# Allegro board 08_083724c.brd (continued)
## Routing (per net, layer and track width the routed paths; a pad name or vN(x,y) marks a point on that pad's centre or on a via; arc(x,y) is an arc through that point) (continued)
DAI1_PIN17: length 16.3
  TOP w0.14: P8.64 26.75,66.79 26.85,66.69 26.85,65.93 v1(26.5,65.58) ; U1.AB19 35.35,59.84 v1(35.13,60.06)
  L3_SIG1 w0.114: v1(26.5,65.58) 26.11,65.2 26.11,64.9 29.52,61.49 33.7,61.49 v1(35.13,60.06)
DAI1_PIN18: length 16.5
  TOP w0.14: v1(26.5,65.07) 27.13,65.71 27.13,66.73 27.25,66.84 P8.66 ; U1.AB18 v1(35.75,59.02)
  L3_SIG1 w0.114: v1(35.75,59.02) 35.75,59.97 33.92,61.8 29.77,61.8 v1(26.5,65.07)
DAI1_PIN19: length 15.1
  TOP w0.14: v1(27.5,65.58) 27.85,65.93 27.85,66.69 27.75,66.79 P8.68 ; U1.AA19 v1(34.95,58.22)
  L5_SIG2 w0.114: v1(34.95,58.22) 33.88,59.28 33.88,60.45 32.64,61.7 31.04,61.7 27.97,64.77 27.97,65.47 27.85,65.58 v1(27.5,65.58)
DAI1_PIN20: length 17.1
  TOP w0.14: v1(27.5,65.07) 28.13,65.71 28.13,66.73 28.25,66.84 P8.70 ; U1.AA18 v1(35.75,58.22)
  L3_SIG1 w0.114: v1(27.5,65.07) 27.5,64.65 30.03,62.12 34.05,62.12 36.14,60.03 36.14,58.61 v1(35.75,58.22)
DMI0_A: length 26.4
  TOP w0.14: U1.A20 v1(34.15,41.42)
  L10_SIG4 w0.109: v1(34.15,41.42) 33.89,41.42 33.73,41.26 33.73,40.69 34.62,39.8 34.62,38.02 34.51,37.92 34.26,37.92 34.16,38.03 34.16,39.69 34.05,39.8 33.83,39.8 33.72,39.69 33.72,38.03 33.61,37.92 33.36,37.92 33.25,38.03 33.25,40.71 33.14,40.82 32.52,40.82 32.41,40.71 32.41,40.27 32.52,40.16 32.8,40.16 32.91,40.05 32.91,39.83 32.8,39.72 32.52,39.72 32.41,39.61 32.41,39.4 32.52,39.29 32.8,39.29 32.91,39.18 32.91,38.96 32.8,38.85 32.52,38.85 32.41,38.74 32.41,32.77 32.52,32.66 35.13,32.66 v1(35.5,32.3)
  BOTTOM w0.14: U3.C3 v1(35.5,32.3)
DMI0_B: length 28.8
  TOP w0.14: U1.B8 v1(44.55,42.22)
  L8_SIG3 w0.109: v1(47.2,32.3) 47.2,31.98 47.12,31.9 46.92,31.9 46.84,31.98 46.84,34.05 47.26,34.47 48.4,34.47 48.5,34.58 48.5,34.99 48.61,35.1 48.83,35.1 48.94,34.99 48.94,34.6 49.05,34.49 49.27,34.49 49.38,34.6 49.38,34.99 49.49,35.1 49.71,35.1 49.81,34.99 49.81,34.6 49.92,34.49 50.14,34.49 50.25,34.6 50.25,34.99 50.36,35.1 50.58,35.1 50.69,34.99 50.69,34.32 50.8,34.21 51.02,34.21 51.13,34.32 51.13,34.99 51.23,35.1 51.45,35.1 51.56,34.99 51.56,34.32 51.67,34.21 52.06,34.21 52.17,34.32 52.17,35.79 51.26,36.7 51.26,39.88 51,40.13 49.48,40.13 48.92,40.69 47.96,40.69 47.37,41.27 47.37,42.49 47.24,42.62 44.96,42.62 v1(44.55,42.22)
  BOTTOM w0.14: U3.Y3 v1(47.2,32.3)
DMI1_A: length 26.7
  TOP w0.14: U1.B15 v1(38.15,42.22)
  L8_SIG3 w0.109: v1(35.5,26.7) 36.27,26.7 36.4,26.82 36.4,26.98 36.29,27.09 35.63,27.09 35.52,27.2 35.52,27.41 35.63,27.52 36.29,27.52 36.4,27.63 36.4,28.5 36.2,28.7 34.62,28.7 34.47,28.85 34.47,30.96 34.34,31.09 33.76,31.09 33.66,31.2 33.66,31.8 33.76,31.9 35.82,31.9 35.92,32 35.92,33.35 35.81,33.46 35.31,33.46 35.2,33.57 35.2,33.8 35.3,33.89 35.71,33.89 35.84,34.02 35.84,34.2 35.71,34.33 35.27,34.33 35.1,34.5 35.1,34.9 35.28,35.08 35.79,35.08 35.94,35.23 35.94,39.42 37.73,41.21 37.73,41.54 38.05,41.86 v1(38.15,42.22)
  BOTTOM w0.14: U3.C10 v1(35.5,26.7)
DMI1_B: length 29
  TOP w0.14: U1.A2 v1(49.35,41.42)
  L10_SIG4 w0.109: v1(46.55,26.7) 46.74,26.88 46.74,27.89 47.04,28.19 49.66,28.19 50.52,29.06 50.52,30.63 50.63,30.74 51.53,30.74 51.64,30.85 51.64,31.07 51.53,31.17 50.6,31.17 50.5,31.28 50.5,31.5 50.6,31.61 51.53,31.61 51.64,31.72 51.64,31.94 51.53,32.05 50.58,32.05 50.47,32.16 50.47,32.38 50.58,32.49 51.53,32.49 51.64,32.59 51.64,32.81 51.53,32.92 50.76,32.92 50.65,33.03 50.65,33.25 50.76,33.36 51.53,33.36 51.64,33.47 51.64,33.69 51.53,33.8 51.26,33.8 51.16,33.9 51.16,34.12 51.64,34.61 51.64,37.89 51.53,38 51.29,38 51.18,38.11 51.18,38.33 51.29,38.44 51.53,38.44 51.64,38.55 51.64,38.77 51.53,38.87 51.29,38.87 51.18,38.98 51.18,39.2 51.29,39.31 51.53,39.31 51.64,39.42 51.64,39.8 50.57,40.87 49.89,40.87 v1(49.35,41.42)
  BOTTOM w0.14: U3.Y10 v1(46.55,26.7)
DQ0_A: length 27
  TOP w0.14: U1.C17 v1(36.55,43.02)
  L10_SIG4 w0.109: v1(36.55,43.02) 36.87,43.02 36.98,42.91 36.98,41.94 36.87,41.83 36.27,41.83 36.14,41.96 36.14,42.42 35.97,42.6 34.81,42.6 34.56,42.34 34.56,40.56 35.27,39.85 35.27,37.91 34.81,37.45 33.16,37.45 32.97,37.26 32.97,37.05 33.14,36.88 34.37,36.88 34.49,36.75 34.49,36.5 34.37,36.37 33.01,36.37 32.91,36.26 32.91,36.04 33.01,35.93 34.37,35.93 34.49,35.8 34.49,35.55 34.37,35.42 33.01,35.42 32.91,35.31 32.91,35.04 33.09,34.86 34.21,34.86 34.41,34.66 34.41,34.44 33.82,33.86 33.06,33.86 32.96,33.75 32.96,33.47 33.1,33.32 33.92,33.32 34.49,33.9 v1(34.85,33.9)
  BOTTOM w0.14: U3.B2 v1(34.85,33.9)
DQ0_B: length 29.5
  TOP w0.14: U1.D7 v1(45.35,43.82)
  L8_SIG3 w0.109: v1(47.85,33.1) 48.23,33.48 49.15,33.48 49.66,32.97 49.66,31.27 50.77,30.15 52.45,30.15 53.67,31.37 53.67,41.07 53.11,41.63 50.87,41.63 50.69,41.81 49.99,41.81 49.73,42.06 49.73,42.47 49.58,42.62 48.44,42.62 48.24,42.82 48.24,43.13 47.96,43.42 46.05,43.42 45.66,43.82 v1(45.35,43.82)
  BOTTOM w0.14: U3.AA2 v1(47.85,33.1)
DQ1_A: length 26.5
  TOP w0.14: U1.E19 v1(34.95,44.62)
  L10_SIG4 w0.109: v1(34.95,44.62) 34.88,44.28 34.56,43.95 34.56,43.54 34.43,43.41 32.9,43.41 32.79,43.3 32.79,42.73 32.9,42.62 33.65,42.62 33.78,42.49 33.78,41.92 33.67,41.81 32.06,41.81 31.95,41.7 31.95,32.34 32.08,32.21 32.36,32.21 32.47,32.1 32.47,31.28 32.58,31.17 32.8,31.17 32.9,31.28 32.9,32.1 33.01,32.21 33.23,32.21 33.34,32.1 33.34,31.28 33.45,31.17 33.67,31.17 33.78,31.28 33.78,31.79 33.89,31.9 35.93,31.9 36.04,32.01 36.04,32.28 35.5,32.83 v1(35.5,33.1)
  BOTTOM w0.14: U3.C2 v1(35.5,33.1)
DQ1_B: length 28.3
  TOP w0.14: U1.C4 v1(47.75,43.02)
  L8_SIG3 w0.109: v1(47.75,43.02) 47.83,42.65 48.13,42.35 48.13,41.22 48.31,41.05 49.17,41.05 49.71,40.51 51.44,40.51 51.69,40.26 51.69,36.91 52.6,35.99 52.6,31.7 52.37,31.47 51.85,31.47 51.56,31.75 51.56,33.72 51.46,33.83 51.24,33.83 51.13,33.72 51.13,31.58 51.02,31.47 50.73,31.47 50.62,31.58 50.62,33.81 50.29,34.14 47.44,34.14 v1(47.2,33.9)
  BOTTOM w0.14: U3.Y2 v1(47.2,33.9)
DQ2_A: length 27.4
  TOP w0.14: U1.D16 v1(37.35,43.82)
  L10_SIG4 w0.109: v1(37.35,43.82) 37.62,43.82 38.02,43.41 38.48,43.41 38.56,43.48 38.56,44.96 38.66,45.06 39.24,45.06 39.34,44.96 39.34,43.51 39.45,43.41 40.06,43.41 40.16,43.51 40.16,44.96 40.26,45.06 40.84,45.06 40.94,44.95 40.94,35.38 40.72,35.15 40.33,35.15 40.22,35.04 40.22,33.61 40.11,33.5 39.89,33.5 39.78,33.61 39.78,35.12 39.68,35.23 38.46,35.23 38.35,35.12 38.35,34.4 38.25,34.29 37.19,34.29 37.08,34.18 37.08,34.18 v1(36.8,33.9)
  BOTTOM w0.14: U3.E2 v1(36.8,33.9)
DQ2_B: length 30.8
  TOP w0.14: U1.C6 v1(46.15,43.02)
  L8_SIG3 w0.109: v1(46.15,43.02) 45.79,43.02 45.39,43.41 44.31,43.41 44.15,43.25 44.15,42.09 44.4,41.83 44.85,41.83 44.96,41.72 44.96,41.1 45.06,41 45.33,41 45.79,40.54 45.79,38.15 45.94,38 49.99,38 50.11,37.87 50.11,36.46 49.98,36.32 49.69,36.32 49.58,36.43 49.58,37.43 49.47,37.54 49.26,37.54 49.15,37.43 49.15,36.43 49.04,36.32 48.82,36.32 48.71,36.43 48.71,37.43 48.6,37.54 48.38,37.54 48.27,37.43 48.27,36.43 48.16,36.32 47.95,36.32 47.84,36.43 47.84,37.43 47.73,37.54 47.51,37.54 47.4,37.43 47.4,36.43 47.29,36.32 47.07,36.32 46.96,36.43 46.96,37.43 46.85,37.54 46.63,37.54 46.53,37.43 46.53,36.62 45.49,35.59 45.49,35.13 45.64,34.98 45.64,34.15 v1(45.9,33.9)
  BOTTOM w0.14: U3.V2 v1(45.9,33.9)
DQ3_A: length 27.2
  TOP w0.14: U1.D18 v1(35.75,43.82)
  L10_SIG4 w0.109: v1(35.75,43.82) 36.16,44.22 37.69,44.22 37.77,44.3 37.77,44.81 38.13,45.16 38.13,45.34 38.23,45.44 41.61,45.44 41.73,45.31 41.73,42.06 41.34,41.67 41.34,35.24 41.12,35.03 41.12,32.11 40.92,31.9 38.51,31.9 38.3,32.11 38.3,33.79 38.19,33.9 v1(37.45,33.9)
  BOTTOM w0.14: U3.F2 v1(37.45,33.9)
DQ3_B: length 28.2
  TOP w0.14: U1.C2 v1(49.35,43.02)
  L8_SIG3 w0.109: v1(45.25,33.9) 45.22,33.9 44.88,34.24 44.88,36.02 45.36,36.5 45.36,36.74 45.26,36.84 44.38,36.84 44.27,36.95 44.27,37.17 44.38,37.28 45.26,37.28 45.36,37.39 45.36,37.79 45.26,37.9 44.25,37.9 44.15,38.01 44.15,38.23 44.25,38.34 45.26,38.34 45.36,38.45 45.36,38.71 45.26,38.81 44.25,38.81 44.15,38.92 44.15,39.14 44.25,39.25 45.26,39.25 45.36,39.36 45.36,39.58 45.26,39.69 44.25,39.69 44.15,39.8 44.15,40.02 44.25,40.13 45.15,40.13 45.26,40.23 45.26,40.45 45.15,40.56 44.4,40.56 44.15,40.82 44.15,41.63 43.94,41.83 43.56,41.83 43.32,42.08 43.32,43.98 43.59,44.25 47.89,44.25 48.16,43.98 48.16,43.66 48.4,43.42 48.95,43.42 v1(49.35,43.02)
  BOTTOM w0.14: U3.U2 v1(45.25,33.9)
DQ4_A: length 26.7
  TOP w0.14: U1.E17 v1(36.55,44.62)
  L10_SIG4 w0.109: v1(36.55,44.62) 36.94,45.01 37.49,45.01 37.74,45.26 37.74,45.67 37.92,45.85 42.44,45.85 42.55,45.74 42.55,42.34 41.76,41.55 41.76,35.07 41.48,34.79 41.48,31.83 40.74,31.09 37.86,31.09 v1(37.45,31.5)
  BOTTOM w0.14: U3.F4 v1(37.45,31.5)
DQ4_B: length 28.2
  TOP w0.14: U1.B1 v1(50.15,42.22)
  L8_SIG3 w0.109: v1(50.15,42.22) 50.87,42.22 51.13,41.96 53.57,41.96 54.18,41.35 54.18,30.28 53.72,29.82 44.55,29.82 44.35,30.02 44.35,31.24 v1(44.6,31.5)
  BOTTOM w0.14: U3.U4 v1(44.6,31.5)
DQ5_A: length 26.6
  TOP w0.14: U1.F18 v1(35.75,45.42)
  L10_SIG4 w0.109: v1(37.45,32.3) 37.79,32.3 37.9,32.41 37.9,33.32 37.71,33.5 36.64,33.5 36.25,33.89 36.25,34.14 37.69,35.59 40.39,35.59 40.54,35.74 40.54,37.77 40.26,38.05 39.81,38.05 39.67,38.18 39.67,39.45 40.06,39.83 40.45,39.83 40.56,39.94 40.56,40.84 40.45,40.94 40.28,40.94 40.16,41.07 40.16,41.72 40.05,41.83 39.43,41.83 39.32,41.94 39.32,42.51 39.21,42.62 38.67,42.62 38.56,42.51 38.56,41.96 38.43,41.83 37.95,41.83 37.74,42.04 37.74,43.18 37.52,43.41 35.5,43.41 35.32,43.59 35.32,44.74 35.66,45.09 v1(35.75,45.42)
  BOTTOM w0.14: U3.E4 v1(37.45,32.3)
DQ5_B: length 28.2
  TOP w0.14: U1.B5 v1(46.95,42.22)
  L8_SIG3 w0.109: v1(45.9,31.5) 46.22,31.69 46.56,32.03 46.56,34.19 47.22,34.85 47.88,34.85 47.96,34.92 47.96,35.36 48.08,35.48 51.4,35.48 51.51,35.59 51.51,35.87 50.88,36.5 50.88,39.55 50.7,39.73 49.33,39.73 49.09,39.97 48.89,39.97 48.78,39.86 48.78,39.1 48.67,38.99 48.46,38.99 48.35,39.1 48.35,40.18 48.24,40.28 48.02,40.28 47.91,40.18 47.91,39.1 47.8,38.99 47.58,38.99 47.47,39.1 47.47,40.58 47.36,40.69 47.15,40.69 47.04,40.58 47.04,39.1 46.93,38.99 46.71,38.99 46.56,39.14 46.56,41.82 v1(46.95,42.22)
  BOTTOM w0.14: U3.V4 v1(45.9,31.5)
DQ6_A: length 28.1
  TOP w0.14: U1.F16 v1(37.35,45.42)
  L10_SIG4 w0.109: v1(37.35,45.42) 36.96,45.81 36.96,46.42 36.75,46.63 35.6,46.63 35.36,46.38 35.36,46.08 35.12,45.83 34.75,45.83 34.54,45.63 34.54,45.26 34.3,45.02 31.88,45.02 31.09,44.22 31.09,31.47 32.26,30.3 35,30.3 35.23,30.53 35.23,31.22 v1(35.5,31.5)
  BOTTOM w0.14: U3.C4 v1(35.5,31.5)
DQ6_B: length 28.3
  TOP w0.14: U1.B7 v1(45.35,42.22)
  L8_SIG3 w0.109: v1(47.2,31.5) 47.58,31.11 48.18,31.11 48.29,31.01 48.29,30.36 48.18,30.25 45.09,30.25 44.86,30.48 44.86,31.22 45.54,31.9 46.02,31.9 46.28,32.16 46.28,34.3 46.18,34.4 46.18,34.9 47.17,35.89 50.41,35.89 50.56,36.04 50.56,38.87 50.29,39.14 49.5,39.14 48.89,38.52 46.41,38.52 46.19,38.74 46.19,40.75 45.75,41.2 45.75,41.82 v1(45.35,42.22)
  BOTTOM w0.14: U3.Y4 v1(47.2,31.5)
DQ7_A: length 26.5
  TOP w0.14: U1.G17 v1(36.55,46.22)
  L10_SIG4 w0.109: v1(36.55,46.22) 36.16,45.82 35.59,45.82 35.33,45.57 35.33,45.24 35.1,45.01 34.76,45.01 34.54,44.79 34.54,44.48 34.29,44.22 31.67,44.22 31.48,44.03 31.48,43.8 31.59,43.69 32.15,43.69 32.26,43.58 32.26,43.36 32.15,43.25 31.59,43.25 31.48,43.15 31.48,42.93 31.59,42.82 32.2,42.82 32.31,42.71 32.31,42.49 32.2,42.38 31.63,42.38 31.52,42.27 31.52,31.7 32.48,30.73 34.09,30.73 v1(34.85,31.5)
  BOTTOM w0.14: U3.B4 v1(34.85,31.5)
DQ7_B: length 28.2
  TOP w0.14: U1.B3 v1(48.55,42.22)
  L8_SIG3 w0.109: v1(47.85,31.5) 48.26,31.9 48.67,31.9 48.87,32.11 48.87,32.49 48.67,32.69 47.68,32.69 47.42,32.94 47.42,33.4 47.83,33.81 49.56,33.81 50.11,33.25 50.11,31.5 50.47,31.14 52.63,31.14 53.11,31.62 53.11,36.42 52.65,36.88 52.65,38.55 52.54,38.66 52.23,38.66 52.12,38.77 52.12,38.98 52.23,39.09 52.54,39.09 52.65,39.2 52.65,39.42 52.54,39.53 52.23,39.53 52.12,39.64 52.12,39.86 52.37,40.11 52.37,40.46 51.89,40.94 49.86,40.94 49.73,41.07 49.73,41.58 49.5,41.81 48.96,41.81 v1(48.55,42.22)
  BOTTOM w0.14: U3.AA4 v1(47.85,31.5)
DQ8_A: length 25.9
  TOP w0.14: U1.B22 v1(32.55,42.22)
  L8_SIG3 w0.109: v1(34.85,25.9) 32.27,25.9 31.95,26.22 31.95,35.66 32.94,36.65 32.94,38.32 32.83,38.43 32.19,38.43 32.08,38.54 32.08,38.76 32.19,38.87 32.83,38.87 32.94,38.98 32.94,39.2 32.83,39.31 32.19,39.31 32.08,39.42 32.08,39.63 32.19,39.74 32.83,39.74 32.94,39.85 32.94,40.07 32.83,40.18 32.19,40.18 32.08,40.29 32.08,40.51 32.19,40.62 32.83,40.62 32.94,40.73 32.94,40.95 32.83,41.05 32.19,41.05 32.08,41.16 32.08,41.74 v1(32.55,42.22)
  BOTTOM w0.14: U3.B11 v1(34.85,25.9)
DQ8_B: length 30.1
  TOP w0.14: U1.F5 v1(46.15,45.42)
  L10_SIG4 w0.109: v1(46.15,45.42) 46.56,45.01 47.14,45.01 47.35,44.81 47.35,44.45 47.57,44.22 49.5,44.22 49.76,43.97 49.76,43.66 50.01,43.41 50.29,43.41 51.94,41.76 52.48,41.76 54,40.23 54,30.25 52.2,28.45 51.99,28.45 49.81,26.26 47.63,26.26 v1(47.2,26.7)
  BOTTOM w0.14: U3.AA11 v1(47.2,26.7)
DQ9_A: length 27.2
  TOP w0.14: U1.B20 v1(34.15,42.22)
  L8_SIG3 w0.109: v1(34.15,42.22) 33.75,42.62 32.13,42.62 31.64,42.13 31.64,38.04 31.76,37.91 32.26,37.91 32.39,37.78 32.39,37.6 32.26,37.47 31.76,37.47 31.64,37.34 31.64,37.16 31.76,37.04 32.26,37.04 32.39,36.91 32.39,36.73 32.26,36.6 31.76,36.6 31.55,36.38 31.55,26.04 32.18,25.4 35.39,25.4 35.5,25.51 v1(35.5,25.9)
  BOTTOM w0.14: U3.C11 v1(35.5,25.9)
DQ9_B: length 30.1
  TOP w0.14: U1.D1 v1(50.15,43.82)
  L10_SIG4 w0.109: v1(47.2,25.9) 50.18,25.9 51.59,27.3 54.2,27.3 54.33,27.43 54.33,27.8 54.22,27.91 53.09,27.91 52.98,28.02 52.98,28.24 53.09,28.35 54.22,28.35 54.33,28.46 54.33,40.79 51.31,43.82 v1(50.15,43.82)
  BOTTOM w0.14: U3.Y11 v1(47.2,25.9)
DQ10_A: length 27.1
  TOP w0.14: U1.B18 v1(35.75,42.22)
  L8_SIG3 w0.109: v1(36.8,25.9) 36.41,26.29 32.49,26.29 32.36,26.42 32.36,26.72 32.47,26.83 33.01,26.83 33.12,26.94 33.12,27.16 33.01,27.27 32.47,27.27 32.36,27.37 32.36,27.59 32.47,27.7 33.01,27.7 33.12,27.81 33.12,28.03 33.01,28.14 32.47,28.14 32.36,28.25 32.36,28.47 32.47,28.58 33.01,28.58 33.12,28.68 33.12,28.9 33.01,29.01 32.47,29.01 32.36,29.12 32.36,35.41 33.48,36.53 33.48,40.03 34.57,41.12 34.57,41.55 34.82,41.81 35.34,41.81 v1(35.75,42.22)
  BOTTOM w0.14: U3.E11 v1(36.8,25.9)
DQ10_B: length 30.1
  TOP w0.14: U1.G6 v1(46.15,46.22)
  L10_SIG4 w0.109: v1(46.15,46.22) 45.47,46.61 ; v1(45.9,25.9) 45.51,25.5 42.49,25.5 41.27,26.72 41.27,28.78 42.24,29.74 42.24,31.65 42.49,31.9 44.09,31.9 44.37,32.18 44.37,40.82 44.15,41.05 44.15,45.29 44.93,46.08 44.93,46.35 45.19,46.61
  L10_SIG4 w0.114: 45.47,46.61 45.19,46.61
  BOTTOM w0.14: U3.V11 v1(45.9,25.9)
DQ11_A: length 27.1
  TOP w0.14: U1.C21 v1(33.35,43.02)
  L8_SIG3 w0.109: v1(33.35,43.02) 31.81,43.02 31.13,42.33 31.13,25.84 31.98,24.99 35.51,24.99 36.03,25.51 37.07,25.51 v1(37.45,25.9)
  BOTTOM w0.14: U3.F11 v1(37.45,25.9)
DQ11_B: length 29.4
  TOP w0.14: U1.E4 v1(47.75,44.62)
  L10_SIG4 w0.109: v1(47.75,44.62) 47.75,44.88 46.81,45.82 45.21,45.82 44.96,45.57 44.96,41.05 44.83,40.92 44.83,32.33 45.09,32.08 45.09,31.11 43.87,29.9 42.82,29.9 41.63,28.7 41.63,27.15 42.49,26.29 44.86,26.29 v1(45.25,25.9)
  BOTTOM w0.14: v1(45.25,25.9) U3.U11
DQ12_A: length 25.1
  TOP w0.14: U1.D20 v1(34.15,43.82)
  L8_SIG3 w0.109: v1(37.44,28.3) 38.12,28.3 38.13,28.3 38.13,28.31 38.23,28.41 38.23,29.74 37.82,30.15 37.82,36.25 37.72,36.35 36.91,36.35 36.8,36.46 36.8,38.71 39.34,41.25 39.34,44.11 39.24,44.22 34.56,44.22 v1(34.15,43.82)
  BOTTOM w0.14: U3.F9 v1(37.44,28.3)
DQ12_B: length 29.3
  TOP w0.14: U1.D5 v1(46.95,43.82)
  L10_SIG4 w0.109: v1(44.6,27.5) 44.86,27.75 44.86,29.34 45.21,29.69 48.72,29.69 49.2,30.18 49.2,33.83 48.69,34.34 48.69,35.56 48.29,35.96 47.1,35.96 46.99,36.07 46.99,36.29 47.1,36.4 48.02,36.4 48.13,36.51 48.13,36.73 48.02,36.84 47.07,36.84 46.96,36.95 46.96,37.16 47.07,37.27 48.02,37.27 48.13,37.38 48.13,37.6 48.02,37.71 47.07,37.71 46.96,37.82 46.96,38.04 47.07,38.15 48.02,38.15 48.13,38.26 48.13,38.46 47.55,39.04 47.55,40.61 47.47,40.69 46.84,40.69 46.56,40.97 46.56,43.42 v1(46.95,43.82)
  BOTTOM w0.14: U3.U9 v1(44.6,27.5)
DQ13_A: length 27.8
  TOP w0.14: U1.A21 v1(33.35,41.42)
  L8_SIG3 w0.109: v1(33.35,41.42) 33.74,41.81 34.26,41.81 34.54,42.09 34.54,43.18 34.8,43.43 38.33,43.43 38.56,43.21 38.56,41.22 36.37,39.04 36.37,35.25 36.58,35.04 36.58,34.32 36.35,34.09 36.35,32.13 36.58,31.9 36.58,31.37 36.3,31.09 35.76,31.09 35.15,30.49 35.15,30.18 35.53,29.79 37.36,29.79 37.9,29.26 37.9,28.98 37.59,28.68 37.18,28.68 v1(36.8,28.3)
  BOTTOM w0.14: U3.E9 v1(36.8,28.3)
DQ13_B: length 29.2
  TOP w0.14: U1.F7 v1(45.35,45.42)
  L10_SIG4 w0.109: v1(45.25,27.5) 44.86,27.1 43.64,27.1 43.54,27.21 43.54,27.78 43.64,27.89 44.25,27.89 44.48,28.12 44.48,29.51 45.05,30.09 48.55,30.09 48.87,30.4 48.87,33.55 47.6,34.82 47.02,34.82 46.53,35.31 46.53,38.73 46.64,38.84 46.96,38.84 47.07,38.95 47.07,39.17 46.96,39.28 46.64,39.28 46.53,39.39 46.53,39.6 46.64,39.71 46.96,39.71 47.07,39.82 47.07,40.04 46.96,40.15 46.64,40.15 45.74,41.05 45.74,45.03 v1(45.35,45.42)
  BOTTOM w0.14: U3.V9 v1(45.25,27.5)
DQ14_A: length 25.9
  TOP w0.14: U1.B16 v1(37.35,42.22)
  L8_SIG3 w0.109: v1(37.35,42.22) 37,42.13 36.68,41.81 36.3,41.81 36.14,41.66 36.14,41.25 35.08,40.18 35.08,39.78 34.97,39.67 34.07,39.67 33.96,39.56 33.96,39.35 34.07,39.24 34.97,39.24 35.08,39.13 35.08,38.91 34.97,38.8 34.07,38.8 33.96,38.69 33.96,38.47 34.07,38.36 34.97,38.36 35.08,38.25 35.08,38.03 34.97,37.93 34.07,37.93 33.96,37.82 33.96,36.32 32.77,35.13 32.77,30.51 32.97,30.3 33.72,30.3 33.83,30.19 33.83,27.31 34.04,27.1 34.39,27.1 35.27,27.98 v1(35.5,28.3)
  BOTTOM w0.14: U3.C9 v1(35.5,28.3)
DQ14_B: length 29.5
  TOP w0.14: U1.D3 v1(48.55,43.82)
  L10_SIG4 w0.109: v1(48.55,43.82) 48.96,43.41 49.58,43.41 49.76,43.23 49.76,42.85 49.99,42.62 50.37,42.62 50.6,42.39 50.6,42.16 53.67,39.09 53.67,33.96 53.56,33.85 53.17,33.85 53.06,33.74 53.06,33.52 53.17,33.41 53.56,33.41 53.67,33.3 53.67,33.09 53.56,32.98 53.17,32.98 53.06,32.87 53.06,32.65 53.17,32.54 53.56,32.54 53.67,32.43 53.67,32.21 53.56,32.1 53.17,32.1 53.06,31.99 53.06,31.78 53.17,31.67 53.56,31.67 53.67,31.56 53.67,31.34 53.56,31.23 53.17,31.23 53.06,31.12 53.06,30.9 53.17,30.79 53.56,30.79 53.67,30.68 53.67,30.53 52.76,29.62 51.6,29.62 51.49,29.51 51.49,28.63 49.96,27.1 47.6,27.1 v1(47.2,27.5)
  BOTTOM w0.14: U3.Y9 v1(47.2,27.5)
DQ15_A: length 26.2
  TOP w0.14: U1.C19 v1(34.95,43.02)
  L8_SIG3 w0.109: v1(34.85,28.3) 34.4,28.3 34.14,28.56 34.14,30.6 34.03,30.71 33.31,30.71 33.2,30.82 33.2,33.38 33.93,34.11 33.93,35.4 34.12,35.59 35.4,35.59 35.51,35.69 35.51,35.97 35.4,36.08 34.55,36.08 34.44,36.19 34.44,36.41 34.55,36.52 35.4,36.52 35.51,36.63 35.51,36.85 35.4,36.95 34.55,36.95 34.44,37.06 34.44,37.28 34.55,37.39 35.4,37.39 35.51,37.5 35.51,39.78 36.96,41.22 36.96,41.58 37.19,41.81 37.49,41.81 37.73,42.05 37.73,42.51 37.62,42.62 35.35,42.62 v1(34.95,43.02)
  BOTTOM w0.14: U3.B9 v1(34.85,28.3)
DQ15_B: length 29.6
  TOP w0.14: U1.E6 v1(46.15,44.62)
  L10_SIG4 w0.109: v1(46.15,44.62) 46.57,44.2 47.11,44.2 47.37,43.93 47.37,42.72 47.47,42.62 49.48,42.62 49.76,42.34 49.76,41.96 49.91,41.81 50.33,41.81 52.65,39.48 52.65,36.59 52.76,36.48 53.18,36.48 53.29,36.37 53.29,36.15 53.18,36.04 52.76,36.04 52.65,35.93 52.65,35.71 52.76,35.6 53.18,35.6 53.29,35.5 53.29,35.28 53.18,35.17 52.76,35.17 52.65,35.06 52.65,34.84 52.76,34.73 53.18,34.73 53.29,34.62 53.29,34.4 53.18,34.29 52.76,34.29 52.65,34.19 52.65,30.23 52.54,30.12 51.09,30.12 50.98,30.02 50.98,28.85 49.99,27.86 48.22,27.86 v1(47.85,27.5)
  BOTTOM w0.14: U3.AA9 v1(47.85,27.5)
DQS0_C_A: length 27.4
  TOP w0.14: U1.A18 v1(35.75,41.42)
  L10_SIG4 w0.107: v1(36.8,33.1) 36.51,32.8 36.39,32.8 36.16,33.03 36.16,33.28 35.74,33.7 35.74,33.74 35.74,33.85 35.71,33.88 35.1,34.49 35.1,34.82 35.28,35 35.28,35.43 35.1,35.61 35.1,35.84 35.3,36.04 35.7,36.04 35.9,35.84 36.26,35.84 36.46,36.04 39.41,36.04 39.64,36.27 39.64,36.99 39.39,37.24 37.05,37.24 36.92,37.37 36.92,37.54 37.05,37.67 38.37,37.67 38.62,37.91 38.62,39.09 38.37,39.34 37.05,39.34 36.92,39.46 36.92,39.64 37.05,39.76 39.39,39.76 39.64,40.01 39.64,40.5 39.37,40.77 35.56,40.77 35.46,40.88 35.46,41.12 v1(35.75,41.42)
  BOTTOM w0.14: U3.E3 v1(36.8,33.1)
DQS0_C_B: length 29.6
  TOP w0.14: U1.A9 v1(43.75,41.42)
  L8_SIG3 w0.107: v1(43.75,41.42) 43.46,41.12 43.46,40.84 43.59,40.71 43.59,40.51 43.46,40.37 43.46,40.18 43.57,40.07 43.57,39.92 43.28,39.62 42.85,39.62 42.67,39.81 42.67,40.14 42.49,40.31 42.21,40.31 42.07,40.17 41.88,40.17 41.74,40.31 41.22,40.31 41.05,40.14 41.05,38 41.16,37.9 43.51,37.9 43.76,37.64 43.76,37.18 43.54,36.96 41.16,36.96 41.05,36.85 41.05,36.64 41.16,36.53 44.02,36.53 44.25,36.3 44.25,35.91 44.02,35.69 41.16,35.69 41.05,35.58 41.05,35.37 41.16,35.26 44.24,35.26 44.53,34.98 44.53,32.62 44.63,32.52 45.17,32.52 45.45,32.8 45.61,32.8 v1(45.9,33.1)
  BOTTOM w0.152: U3.V3 v1(45.9,33.1)
DQS0_T_A: length 27.4
  TOP w0.14: U1.A19 v1(34.95,41.42)
  L10_SIG4 w0.107: v1(36.8,32.3) 36.51,32.59 36.31,32.59 35.95,32.94 35.95,33.2 35.53,33.61 35.53,33.77 35.5,33.8 35.5,33.8 34.89,34.41 34.89,35.93 35.21,36.25 39.32,36.25 39.43,36.35 39.43,36.91 39.3,37.03 36.96,37.03 36.72,37.28 36.72,37.63 36.96,37.88 38.29,37.88 38.41,38 38.41,39 38.29,39.13 36.96,39.13 36.72,39.37 36.72,39.72 36.96,39.97 39.3,39.97 39.43,40.1 39.43,40.41 39.28,40.56 35.48,40.56 35.25,40.79 35.25,41.12 v1(34.95,41.42)
  BOTTOM w0.14: U3.D3 v1(36.8,32.3)
DQS0_T_B: length 29.6
  TOP w0.14: U1.A10 v1(42.95,41.42)
  L8_SIG3 w0.107: v1(45.9,32.3) 45.61,32.59 45.54,32.59 45.25,32.31 44.55,32.31 44.32,32.54 44.32,34.89 44.16,35.05 41.07,35.05 40.84,35.28 40.84,35.67 41.07,35.89 43.93,35.89 44.04,36 44.04,36.21 43.93,36.32 41.07,36.32 40.84,36.55 40.84,36.94 41.07,37.16 43.45,37.16 43.56,37.27 43.56,37.56 43.43,37.69 41.07,37.69 40.84,37.92 40.84,40.22 41.14,40.52 42.58,40.52 42.88,40.22 42.88,39.89 42.94,39.83 43.2,39.83 43.25,39.88 43.25,41.12 v1(42.95,41.42)
  BOTTOM w0.14: U3.W3 v1(45.9,32.3)
DQS1_C_A: length 26.7
  TOP w0.14: U1.A13 v1(39.75,41.42)
  L8_SIG3 w0.107: v1(39.75,41.42) 40.05,41.12 40.05,40.44 39.93,40.33 39.53,40.33 39.42,40.22 39.42,39.82 39.3,39.7 38.91,39.7 38.76,39.55 38.76,39.16 38.6,39 38.49,39 38.21,39 38.1,38.89 38.1,38.5 37.97,38.36 37.97,37.94 38.34,37.56 39.61,37.56 39.87,37.3 39.87,35.66 39.65,35.44 38.47,35.44 38.16,35.13 38.16,30.32 39.04,29.43 41.1,29.43 41.27,29.27 41.27,27.95 41.01,27.69 37.72,27.69 37.23,27.2 36.91,27.2 36.8,27.31 v1(36.8,27.5)
  BOTTOM w0.14: U3.E10 v1(36.8,27.5)
DQS1_C_B: length 30.3
  TOP w0.14: U1.A3 v1(48.55,41.42)
  L10_SIG4 w0.107: v1(45.9,26.7) 45.9,26.95 46.32,27.37 46.32,27.94 46.9,28.52 49.04,28.52 49.87,29.35 49.87,33.6 49.98,33.71 50.46,33.71 50.71,33.95 50.71,34.3 50.46,34.55 49.53,34.55 49.42,34.66 49.42,34.87 49.53,34.98 50.46,34.98 50.71,35.22 50.71,35.57 50.46,35.82 49.53,35.82 49.42,35.93 49.42,36.14 49.53,36.25 50.46,36.25 50.71,36.49 50.71,36.84 50.46,37.09 49.53,37.09 49.42,37.2 49.42,37.41 49.53,37.52 50.46,37.52 50.71,37.76 50.71,38.11 50.46,38.36 49.53,38.36 49.42,38.47 49.42,38.68 49.53,38.79 50.46,38.79 50.71,39.03 50.71,39.38 50.46,39.63 48.36,39.63 48.26,39.74 48.26,41.12 v1(48.55,41.42)
  BOTTOM w0.14: U3.V10 v1(45.9,26.7)
DQS1_T_A: length 26.3
  TOP w0.14: U1.A12 v1(40.55,41.42)
  L8_SIG3 w0.107: v1(36.8,26.7) 36.8,26.88 36.91,26.99 37.31,26.99 37.8,27.48 41.1,27.48 41.48,27.86 41.48,29.35 41.19,29.64 39.13,29.64 38.37,30.4 38.37,35.04 38.56,35.23 39.74,35.23 40.08,35.57 40.08,37.39 39.7,37.77 38.43,37.77 38.18,38.02 38.18,38.28 40.26,40.36 40.26,41.12 v1(40.55,41.42)
  BOTTOM w0.14: U3.D10 v1(36.8,26.7)
DQS1_T_B: length 29.4
  TOP w0.14: U1.A4 v1(47.75,41.42)
  L10_SIG4 w0.107: v1(47.75,41.42) 48.05,41.12 48.05,39.65 48.28,39.42 50.37,39.42 50.5,39.3 50.5,39.12 50.37,38.99 49.44,38.99 49.22,38.77 49.22,38.38 49.44,38.15 50.37,38.15 50.5,38.03 50.5,37.85 50.37,37.72 49.44,37.72 49.22,37.5 49.22,37.11 49.44,36.88 50.37,36.88 50.5,36.76 50.5,36.58 50.37,36.45 49.44,36.45 49.22,36.23 49.22,35.84 49.44,35.61 50.37,35.61 50.5,35.49 50.5,35.31 50.37,35.18 49.44,35.18 49.22,34.96 49.22,34.57 49.44,34.34 50.37,34.34 50.5,34.22 50.5,34.04 50.37,33.91 49.89,33.91 49.66,33.69 49.66,29.43 48.96,28.73 46.81,28.73 46.11,28.03 46.11,27.7 v1(45.9,27.5)
  BOTTOM w0.14: U3.W10 v1(45.9,27.5)
EEPROM_ID0: length 17.8
  TOP w0.127: R95.2 69.88,62.27 U15.1
  TOP w0.14: U15.1 72.48,62.27 72.72,62.03 72.72,59.87 72.95,59.64 76.37,59.64 76.66,59.93 76.66,66.6 76.75,66.69 P8.264
EEPROM_ID1: length 16.7
  TOP w0.127: R96.2 69.88,60.37 U15.3
  TOP w0.14: U15.3 72.07,60.37 72.26,60.18 72.26,59.79 72.75,59.31 76.5,59.31 77.03,59.84 77.03,66.47 77.25,66.68 P8.266
EMSI0_CLK: length 15.4
  TOP w0.14: v2(29.92,13.39) 30.84,14.3 30.84,16.53 29.41,17.96 TP42.1
  BOTTOM w0.14: U7.2 27.45,14.33 27.75,14.03 R176.2 v2(29.92,13.39)
EMSI0_CLK_X: length 66.9
  TOP w0.14: U1.U8 v1(43.75,55.02)
  L10_SIG4 w0.114: v2(25.86,13) 27.31,14.46 27.31,21.36 26.78,21.89 26.78,32.02 24.29,34.51 24.29,48.47 31.24,55.42 33.5,55.42 33.76,55.68 33.76,56.01 33.96,56.21 34.26,56.21 34.54,56.49 34.54,56.82 34.75,57.02 35.1,57.02 35.33,57.25 35.33,57.56 35.59,57.81 35.92,57.81 36.17,58.06 36.17,58.34 36.43,58.6 36.75,58.6 36.98,58.83 36.98,59.16 37.2,59.37 40.81,59.37 41.53,58.65 41.53,58.24 41.96,57.81 42.29,57.81 42.55,57.56 42.55,57.28 42.8,57.02 43.15,57.02 43.36,56.82 43.36,55.41 v1(43.75,55.02)
  BOTTOM w0.14: v2(25.86,13) 26.24,13.39 R176.1
EMSI0_CMD: length 69.4
  TOP w0.14: TP41.1 23.57,17 v2(23.77,16.8) ; U1.U7 v1(45.33,54.99)
  L10_SIG4 w0.114: v1(45.33,54.99) 44.78,54.99 44.15,55.63 44.15,56.77 43.92,57 43.61,57 43.33,57.28 43.33,57.58 43.1,57.81 42.75,57.81 42.55,58.01 42.55,58.37 41.22,59.69 36.7,59.69 36.17,59.16 36.17,58.88 35.92,58.62 35.61,58.62 35.33,58.34 35.33,58.06 35.08,57.81 34.75,57.81 34.57,57.63 34.57,57.28 34.29,57 33.99,57 33.76,56.77 33.76,56.49 33.48,56.21 32.11,56.21 31.75,56.57 31.34,56.57 30.71,55.93 30.71,55.35 23.97,48.61 23.97,34.35 26.46,31.86 26.46,21.75 26.95,21.26 26.95,19 24.75,16.8 v2(23.77,16.8)
  BOTTOM w0.14: U7.5 25.47,17.29 24.98,16.8 v2(23.77,16.8)
EMSI0_CMD_EMMC: length 20.8
  L3_SIG1 w0.114: v2(25.99,14.07) 25.99,15.17 28.33,17.51 34.18,17.51 35.26,16.43 35.26,15.29 34.87,14.91 34.87,13.77 35.38,13.26 35.38,12.62 35.64,12.37 36.29,12.37 v1(36.42,12.24)
  BOTTOM w0.14: U7.4 26.65,16.47 25.99,15.81 v2(25.99,14.07) ; U10.M5 v1(36.42,12.24)
EMSI0_D0: length 89.2
  TOP w0.14: U1.U10 v1(42.15,55.02) ; TP19.1 19.93,17.36 19.93,14.49 21.67,12.75 23.7,12.75 24.46,11.99 v2(24.46,8.12)
  L10_SIG4 w0.114: v1(42.15,55.02) 41.69,55.48 41.69,56.84 40.72,57.81 37.21,57.81 36.98,57.58 36.98,57.2 36.8,57.02 36.45,57.02 36.17,56.74 36.17,56.46 35.89,56.18 35.61,56.18 35.36,55.93 35.36,55.68 35.1,55.42 34.8,55.42 34.54,55.17 34.54,54.89 34.26,54.61 34.01,54.61 33.55,54.15 31.95,54.15 31.61,53.81 30.52,53.81 26.9,50.19 26.9,48.9 25.85,47.85 25.85,44.77 25.06,43.98 25.06,34.7 27.48,32.28 27.48,22.17 28.71,20.94 28.71,18.78 28.39,18.46 28.39,15.55 28.79,15.15 28.79,14.06 26.9,12.17 25.46,12.17 24.89,12.74 24.89,13.54 24.54,13.89 23.29,13.89 22.68,13.28 22.68,9.89 v2(24.46,8.12)
  BOTTOM w0.14: v2(24.46,8.12) 24.22,8.36 U8.2
EMSI0_D1: length 86.6
  TOP w0.14: TP34.1 19.13,16.31 19.13,14.02 20.53,12.61 v2(20.53,9.31) ; U1.U9 v1(42.95,55.02)
  L10_SIG4 w0.114: v2(20.53,9.31) 21.47,9.31 23.24,7.54 24.61,7.54 25.22,8.15 25.22,8.99 25.81,9.58 28.27,9.58 30.56,11.86 30.56,16.82 29.44,17.93 29.44,21.49 28.14,22.78 28.14,34.34 27,35.48 27,39.93 27.71,40.64 27.71,45.16 27,45.87 27,48.1 27.54,48.64 27.54,49.85 30.71,53.02 34.33,53.02 34.57,53.25 34.57,53.61 34.78,53.82 35.1,53.82 35.36,54.08 35.36,54.43 35.53,54.61 36.04,54.61 36.17,54.74 36.17,55.19 36.4,55.42 36.83,55.42 36.98,55.58 36.98,55.93 37.26,56.21 40.74,56.21 40.97,55.98 40.97,54.79 41.15,54.61 42.55,54.61 v1(42.95,55.02)
  BOTTOM w0.14: U8.5 22.23,9.8 21.74,9.31 v2(20.53,9.31)
EMSI0_D2: length 82.4
  TOP w0.14: U1.V11 v1(42.15,55.82) ; v2(21.38,11) 21.03,11.35 21.03,12.75 19.51,14.27 19.51,17.45 TP35.1
  L10_SIG4 w0.114: v1(42.15,55.82) 42.55,56.21 42.55,56.83 42.35,57.02 41.99,57.02 41.07,57.94 41.07,58.27 40.74,58.6 37.24,58.6 36.96,58.32 36.96,58.01 36.75,57.81 36.45,57.81 36.17,57.53 36.17,57.25 35.92,57 35.61,57 35.36,56.74 35.36,56.46 35.13,56.24 34.82,56.24 34.54,55.96 34.54,55.65 34.32,55.42 34.04,55.42 33.76,55.14 33.76,54.89 33.48,54.61 32.23,54.61 31.8,55.04 31.31,55.04 25.53,49.26 25.53,45.01 24.61,44.09 24.61,34.7 27.13,32.18 27.13,22.02 27.63,21.52 27.63,13.99 26.13,12.49 25.59,12.49 25.32,12.76 25.32,14.22 24.56,14.99 23.83,14.99 21.38,12.54 v2(21.38,11)
  BOTTOM w0.14: v2(21.38,11) 21.78,10.6 U8.7
EMSI0_D3: length 75.6
  TOP w0.14: U1.U11 v1(41.37,54.99) ; TP36.1 20.26,16.17 20.26,14.79 21.74,13.31 v2(23.45,13.31)
  L10_SIG4 w0.114: v2(23.45,13.31) 24.91,11.86 27.12,11.86 29.13,13.87 29.13,15.57 28.71,16 28.71,18.27 29.08,18.64 29.08,21.21 27.81,22.49 27.81,32.52 25.37,34.95 25.37,42.7 26.64,43.97 26.64,48.19 27.22,48.77 27.22,49.98 30.7,53.45 31.79,53.45 32.16,53.82 34.29,53.82 34.54,54.08 34.54,54.38 34.77,54.61 35.07,54.61 35.36,54.89 35.36,55.17 35.61,55.42 35.9,55.42 36.17,55.69 36.17,55.93 36.45,56.21 36.75,56.21 36.98,56.44 36.98,56.74 37.26,57.02 40.69,57.02 41.37,56.34 v1(41.37,54.99)
  BOTTOM w0.14: v2(23.45,13.31) 23.45,12.83 23.82,12.46 U8.10
EMSI0_D4: length 67.6
  TOP w0.14: U1.V12 v1(40.55,55.82)
  L3_SIG1 w0.114: v1(35.42,7.71) 34.65,6.94 34.65,5.23 v2(36.02,3.86)
  L10_SIG4 w0.114: v1(40.55,55.82) 40.16,55.42 37.97,55.42 37.74,55.19 37.74,54.84 37.52,54.61 37.19,54.61 36.96,54.38 36.96,54.05 36.72,53.82 36.42,53.82 36.15,53.55 36.15,53.23 35.93,53.01 35.59,53.01 35.36,52.78 35.36,52.48 35.1,52.22 34.77,52.22 34.55,51.99 34.55,51.67 34.3,51.42 30,51.42 28.82,50.23 28.82,48.07 28.47,47.73 28.47,40.39 27.64,39.55 27.64,35.93 28.78,34.79 28.78,23.29 30.15,21.92 30.15,20.07 31.14,19.08 32.94,19.08 33.48,18.54 33.48,10.34 35.42,8.4 v1(35.42,7.71)
EMSI0_D5: length 66.9
  TOP w0.14: U1.U13 v1(39.75,55.02)
  L3_SIG1 w0.114: v1(35.92,7.71) 35.92,7.32 35.76,7.16 35.31,7.16 35,6.86 35,5.89 36.65,4.24 v2(36.65,2.34)
  L10_SIG4 w0.114: v1(39.75,55.02) 39.35,54.62 39.35,54.06 39.11,53.82 38.83,53.82 38.56,53.54 38.56,53.26 38.3,53.01 38,53.01 37.74,52.76 37.74,52.48 37.49,52.22 37.24,52.22 36.96,51.94 36.96,51.56 36.8,51.41 36.37,51.41 36.17,51.21 36.17,50.85 35.1,49.78 31.92,49.78 29.43,47.29 29.43,39.82 28.59,38.98 28.59,36.43 29.73,35.29 29.73,26.21 36.27,19.67 36.27,16.37 34.47,14.57 34.47,12.34 35.56,11.25 36.02,11.25 36.32,10.95 36.32,8.12 v1(35.92,7.71)
EMSI0_D6: length 67.2
  TOP w0.14: U1.U16 v1(37.35,55.02)
  L3_SIG1 w0.114: v1(36.42,7.71) 36.87,7.26 37.5,7.26 37.8,6.97 v2(37.8,3.86)
  L10_SIG4 w0.114: v1(37.35,55.02) 37.01,54.91 36.7,54.61 36.4,54.61 36.14,54.36 36.14,54.05 35.92,53.82 35.61,53.82 35.35,53.56 35.35,53.23 35.15,53.04 34.82,53.04 34.57,52.78 34.57,52.48 34.31,52.22 30.36,52.22 28.5,50.36 28.5,48.2 28.02,47.73 27.58,47.73 27.37,47.51 27.37,46.04 28.03,45.38 28.03,40.45 27.32,39.74 27.32,35.8 28.46,34.66 28.46,23.07 29.79,21.74 29.79,19.86 30.94,18.72 32.74,18.72 33.15,18.31 33.15,8.89 34.77,7.26 36.3,7.26 36.42,7.38 v1(36.42,7.71)
EMSI0_D7: length 67
  TOP w0.14: U1.U12 v1(40.55,55.02)
  L3_SIG1 w0.114: v2(38.43,2.34) 38.43,7.01 37.73,7.71 v1(36.92,7.71)
  L10_SIG4 w0.114: v1(40.55,55.02) 40.15,54.62 40.15,54.05 39.92,53.82 39.62,53.82 39.34,53.54 39.34,53.19 39.16,53.01 38.81,53.01 38.56,52.76 38.56,52.37 38.38,52.2 38,52.2 37.74,51.94 37.74,51.64 37.49,51.38 37.16,51.38 36.96,51.18 36.96,50.77 36.12,49.94 35.71,49.94 35.35,49.58 35.35,49.17 35.2,49.02 32.28,49.02 29.74,46.48 29.74,39.63 28.91,38.79 28.91,36.57 30.05,35.42 30.05,26.41 38.79,17.68 38.79,9.17 37.33,7.71 v1(36.92,7.71)
EMSI0_DS: length 56.3
  TOP w0.14: U1.U14 v1(38.95,55.02)
  L10_SIG4 w0.114: v1(35.92,10.71) 35.56,10.71 34.14,12.14 34.14,14.81 35,15.67 35,20.47 29.41,26.06 29.41,35.05 28.27,36.19 28.27,39.17 29.11,40.01 29.11,47.42 31.85,50.16 34.7,50.16 35.36,50.83 35.36,51.16 35.61,51.41 35.89,51.41 36.17,51.69 36.17,51.97 36.42,52.22 36.7,52.22 36.96,52.48 36.96,52.73 37.24,53.01 37.54,53.01 37.74,53.21 37.74,53.61 37.95,53.82 38.36,53.82 38.55,54.01 38.55,54.62 v1(38.95,55.02)
  BOTTOM w0.14: U10.H5 v1(35.92,10.71)
EMSI0_RST*: length 57.9
  TOP w0.14: TP44.1 R154.2 R157.2 v2(34.49,15.98) ; U1.U15 v1(38.15,55.02)
  L3_SIG1 w0.114: v1(35.92,11.71) 35.4,11.71 33.99,13.13 33.99,15.48 v2(34.49,15.98)
  L10_SIG4 w0.114: v1(38.15,55.02) 38.02,54.66 37.75,54.39 37.75,54.11 37.46,53.82 37.26,53.82 36.96,53.52 36.96,53.29 36.68,53.01 36.37,53.01 36.17,52.81 36.17,52.48 35.91,52.22 35.56,52.22 35.36,52.01 35.36,51.66 35.13,51.44 34.8,51.44 33.88,50.52 31.76,50.52 28.79,47.55 28.79,40.2 27.95,39.36 27.95,36.06 29.1,34.92 29.1,25.87 33.99,20.98 33.99,19.58 34.49,19.08 v2(34.49,15.98)
  BOTTOM w0.14: U10.K5 v1(35.92,11.71)
HADC_VIN0: length 22.5
  TOP w0.14: P8.74 29.25,66.79 29.35,66.69 29.35,65.72 29.21,65.58 v1(29,65.58) ; U1.L22 v1(32.55,49.42)
  L8_SIG3 w0.114: v1(29,65.58) 28.66,65.58 27.74,64.66 27.74,54.23 v1(32.55,49.42)
HADC_VIN1: length 19.6
  TOP w0.14: v1(29,65.07) 29.41,65.07 29.63,65.29 29.63,66.73 29.75,66.84 P8.76 ; v1(30.05,55.3) 31.57,55.3 32.65,54.22 33.35,54.22 U1.T21
  L8_SIG3 w0.114: v1(29,65.07) 29,60.09 28.45,59.54 28.45,55.59 28.74,55.3 v1(30.05,55.3)
HADC_VIN2: length 21.9
  TOP w0.14: v1(30,65.58) 30.35,65.93 30.35,66.69 30.25,66.79 P8.78 ; U1.L21 v1(33.35,49.42)
  L8_SIG3 w0.114: v1(30,65.58) 29.6,65.58 29.49,65.47 29.49,64.35 29.69,64.14 29.69,56.18 30.59,55.28 30.59,51.9 32.38,50.11 32.65,50.11 v1(33.35,49.42)
HADC_VIN3: length 20.7
  TOP w0.14: P8.80 30.75,66.84 30.63,66.73 30.63,65.71 v1(30,65.07) ; U1.M21 v1(33.35,51.02)
  L8_SIG3 w0.114: v1(30,65.07) 30,64.36 30.12,64.24 30.12,56.26 30.99,55.4 30.99,52.04 32.49,50.55 32.88,50.55 v1(33.35,51.02)
HADC_VIN4: length 17.2
  TOP w0.14: U1.R21 v1(33.35,53.42) ; v1(31,65.58) 31.35,65.93 31.35,66.69 31.25,66.79 P8.82
  L8_SIG3 w0.114: v1(33.35,53.42) 32.97,53.8 32.97,53.95 30.56,56.36 30.56,65.47 30.67,65.58 v1(31,65.58)
HADC_VIN5: length 18.5
  TOP w0.14: U1.P21 v1(33.35,52.62) ; v1(31,65.07) 31.63,65.71 31.63,66.73 31.75,66.84 P8.84
  L8_SIG3 w0.114: v1(31,65.07) 31,57.29 32.02,56.27 32.02,55.81 32.42,55.42 33.49,55.42 33.75,55.15 33.75,53.02 v1(33.35,52.62)
HADC_VIN6: length 19.8
  TOP w0.14: v1(32,65.58) 32.21,65.58 32.35,65.72 32.35,66.69 32.25,66.79 P8.86 ; U1.N21 v1(33.35,51.82)
  L8_SIG3 w0.114: v1(33.35,51.82) 33.75,52.22 34.19,52.22 34.55,52.58 34.55,58.44 33.43,59.56 33.43,62.78 31.5,64.71 31.5,65.47 31.61,65.58 v1(32,65.58)
HADC_VIN7: length 22.1
  TOP w0.14: U1.M22 v1(32.55,51.02) ; v1(32,65.07) 32.33,65.07 32.63,65.37 32.63,66.73 32.75,66.84 P8.88
  L8_SIG3 w0.114: v1(32,65.07) 32,64.78 33.86,62.92 33.86,59.66 34.72,58.8 34.98,58.8 35.35,58.43 35.35,52.45 35.12,52.22 34.77,52.22 34.55,52 34.55,51.62 34.35,51.42 32.95,51.42 v1(32.55,51.02)
JTG1_TCK: length 42.9
  TOP w0.14: U1.J6 v1(46.15,47.82)
  L3_SIG1 w0.114: v1(46.15,47.82) 46.52,47.92 46.82,48.22 47.89,48.22 48.15,48.48 48.15,48.76 48.41,49.02 48.7,49.02 48.95,48.76 48.95,48.46 49.19,48.22 58.34,48.22 60.27,46.29 71.28,46.29 72.09,47.09 72.09,49.12 74.83,51.87 P5.4
  BOTTOM w0.14: P5.4 77.04,50.98 77.04,48.57 77.42,48.18 JP5.2
JTG1_TDI: length 41.8
  TOP w0.14: U1.H5 v1(46.95,47.02)
  L3_SIG1 w0.114: v2(75.18,49.28) 75.18,47.51 73.25,45.57 60.09,45.57 58.39,47.27 50.93,47.27 50.29,46.63 49.17,46.63 48.95,46.86 48.95,47.14 48.67,47.42 48.41,47.42 48.15,47.16 48.15,46.81 47.96,46.62 47.35,46.62 v1(46.95,47.02)
  BOTTOM w0.14: JP7.2 75.18,47.34 v2(75.18,49.28) 75.18,51.66 P5.8
JTG1_TDO: length 40.3
  TOP w0.14: U1.F3 v1(48.55,45.42)
  L3_SIG1 w0.114: v2(76.28,48.25) 76.28,43.97 75.95,43.64 75.54,43.64 74.74,44.44 55.51,44.44 54.98,44.97 51.17,44.97 50.34,45.8 49.2,45.8 48.93,45.53 v1(48.55,45.42)
  BOTTOM w0.14: P5.6 76.28,51.49 v2(76.28,48.25) JP3.2
JTG1_TMS: length 41.2
  TOP w0.14: U1.H6 v1(46.15,47.02)
  L3_SIG1 w0.114: v1(46.15,47.02) 46.55,47.42 47.87,47.42 48.15,47.69 48.15,47.97 48.39,48.22 48.71,48.22 48.95,47.97 48.95,47.67 49.21,47.42 50.51,47.42 50.83,47.73 58.38,47.73 60.18,45.92 73.15,45.92 74.63,47.4 74.63,49.56 75.67,50.6 P5.2
  BOTTOM w0.14: P5.2 77.93,48.82 78.56,48.18 JP4.2
JTG1_TRST*: length 56.1
  TOP w0.14: U1.G5 v1(46.95,46.22)
  L3_SIG1 w0.114: v1(46.95,46.22) 47.35,45.82 47.9,45.82 48.15,46.07 48.15,46.35 48.42,46.62 48.71,46.62 48.97,46.35 50.5,46.35 50.97,46.83 58.32,46.83 59.94,45.21 73.34,45.21 75.51,47.39 75.51,48.49 76.61,49.58 79.3,49.58 79.99,50.27 79.99,54.88 P5.9
  BOTTOM w0.14: JP6.2 80.85,54.03 P5.9 78.56,56.31 R15.1 R14.2
JTG_TCK: length 100.9
  TOP w0.14: P8.138 45.25,66.84 45.13,66.73 45.13,65.71 v1(44.5,65.07) ; P4.4 76.53,39.17 76.53,43.23 77.24,43.94 77.24,45.02 77.48,45.26 v2(77.8,45.26) ; U1.F2 v1(49.35,45.42)
  L3_SIG1 w0.114: v1(49.35,45.42) 50.34,45.42 51.1,44.65 54.79,44.65 55.32,44.12 74.4,44.12 75.29,43.23 76.02,43.23 77.04,44.25 77.04,44.5 v2(77.8,45.26)
  L10_SIG4 w0.114: P4.4 74.9,40.79 74.9,44.65 76.66,46.41 76.66,48.87 76.06,49.47 76.06,56.4 68.91,63.55 68.12,63.55 67.47,64.2 57.44,64.2 56.39,65.25 48.87,65.25 48.32,64.71 44.87,64.71 v1(44.5,65.07)
  BOTTOM w0.14: v2(77.8,45.26) 77.42,45.64 JP5.1
JTG_TDI: length 87.7
  TOP w0.14: P8.142 46.25,66.84 46.13,66.73 46.13,65.71 v1(45.5,65.07) ; U1.E2 v1(49.35,44.62)
  L3_SIG1 w0.114: v1(49.35,44.62) 49.75,44.22 50.3,44.22 50.93,43.59 54.14,43.59 56.27,41.45 75.59,41.45 76.73,40.31 P4.8
  L10_SIG4 w0.114: P4.8 75.9,42.34 75.9,42.98 75.3,43.57 75.3,44.55 76.98,46.22 76.98,49 76.38,49.61 76.38,56.62 69.06,63.94 68.28,63.94 67.66,64.55 57.59,64.55 56.59,65.56 48.64,65.56 48.03,64.95 46.05,64.95 45.92,65.07 v1(45.5,65.07)
JTG_TDO: length 87.1
  TOP w0.14: U1.F4 v1(47.75,45.42) ; P8.140 45.75,66.79 45.85,66.69 45.85,65.93 v1(45.5,65.58)
  L3_SIG1 w0.114: v1(47.75,45.42) 48.11,45.49 48.43,45.82 48.74,45.82 49,46.08 50.46,46.08 50.81,45.73 51.47,45.73 52.21,46.47 58.16,46.47 59.77,44.86 75.16,44.86 v2(75.77,44.25)
  L10_SIG4 w0.114: v1(45.5,65.58) 45.85,65.58 46.23,65.2 47.8,65.2 48.41,65.81 48.41,66.55 49.05,67.18 66.75,67.18 67.97,65.96 67.97,64.92 68.58,64.31 70.18,64.31 71.07,63.42 71.07,62.66 76.7,57.04 76.7,49.83 77.3,49.23 77.3,45.78 v2(75.77,44.25)
  BOTTOM w0.14: JP3.1 76.28,45.14 JP8.1 76.27,44.39 76.13,44.25 v2(75.77,44.25)
JTG_TMS: length 108.7
  TOP w0.14: v1(44.5,65.58) 44.85,65.93 44.85,66.69 44.75,66.79 P8.136 ; U1.E3 v1(48.55,44.62) ; P4.2 76.02,38.4 76.02,43.36 76.91,44.25 76.91,45.9 77.16,46.15 78,46.15 v2(78.56,45.59)
  L3_SIG1 w0.114: v2(78.56,45.59) 78.56,44.27 78.26,43.97 77.37,43.97 75.49,42.09 75.11,42.09 73.43,43.76 55.11,43.76 54.57,44.3 51.05,44.3 50.34,45.02 48.95,45.02 v1(48.55,44.62)
  L10_SIG4 w0.114: P4.2 74.57,39.85 74.57,44.83 75.74,46 75.74,52.4 73.79,54.36 73.79,57 68.99,61.8 63.4,61.8 61.96,63.23 58.88,63.23 58.24,62.6 51.07,62.6 49.86,63.8 49.86,64.5 49.54,64.82 48.97,64.82 48.59,64.44 44.58,64.44 44.12,64.9 44.12,65.47 44.23,65.58 v1(44.5,65.58)
  BOTTOM w0.14: JP4.1 v2(78.56,45.59)
JTG_TRST*: length 95.4
  TOP w0.14: P8.144 46.75,66.79 46.85,66.69 46.85,65.93 v1(46.5,65.58) ; U1.E1 v1(50.15,44.62)
  L3_SIG1 w0.114: v1(50.15,44.62) 50.48,44.44 50.98,43.94 54.36,43.94 55.73,42.56 56.67,42.56 57.47,41.77 76.75,41.77 77.57,42.6 79.08,42.6 79.2,42.48 P4.9
  L10_SIG4 w0.114: P4.9 79.2,47.78 77.04,49.94 77.04,57.33 71.45,62.92 71.45,63.55 70.33,64.67 69.85,64.67 68.88,65.63 68.88,66.62 67.97,67.54 47.96,67.54 46.5,66.08 v1(46.5,65.58)
  BOTTOM w0.14: JP6.1 80.85,43.99 80.35,43.49 R10.2 R13.1 78.56,42.21 P4.9
LPDDR4_RESET*: length 30.1
  TOP w0.14: U1.B4 v1(47.75,42.22)
  TOP w0.191: R97.1 v1(43,23.31)
  L3_SIG1 w0.109: v1(43,23.31) 47.41,23.31 51.18,27.08 51.18,38.79 48.95,41.02 48.95,41.61 48.72,41.83 48.13,41.83 v1(47.75,42.22)
  BOTTOM w0.191: R150.2 48.15,40.75 48.15,41.82 v1(47.75,42.22)
LPDDR4_RESET*_X: length 2.3
  TOP w0.191: R97.2 44.6,24.76 v1(44.6,25.9)
  BOTTOM w0.14: U3.T11 v1(44.6,25.9)
NVT_VCCB: length 2.3
  TOP w0.305: v1(18.49,5.13) 18.5,5.12 C66.1
  L3_SIG1 w0.254: v1(17.04,4.51) 17.34,4.81
  L3_SIG1 w0.305: 17.34,4.81 18.17,4.81 v1(18.49,5.13)
ODT_CA_A: length 2.5
  TOP w0.305: R149.1 38.3,35.09 38.3,34.34 v1(38.75,33.9)
  BOTTOM w0.14: U3.G2 v1(38.75,33.9)
ODT_CA_B: length 2.7
  TOP w0.305: R148.1 44.01,35.48 44.4,35.09 44.4,34.34 v1(43.95,33.9)
  BOTTOM w0.14: U3.T2 v1(43.95,33.9)
PA_00/UART0_TXB/FPLL2_DBG_LOCK: length 73.6
  TOP w0.14: P8.188 v1(57.75,66.55) ; U1.T5 v1(46.95,54.22)
  L5_SIG2 w0.114: v1(46.95,54.22) 47.35,54.61 47.9,54.61 48.16,54.86 48.16,55.21 48.37,55.42 48.69,55.42 48.95,55.68 48.95,55.96 49.2,56.21 49.5,56.21 49.76,56.46 49.76,56.82 50.11,57.18 50.11,57.81 50.32,58.01 51.31,58.01 51.79,58.5 51.79,59.36 49.73,61.42 49.73,64.62 50.57,65.46 56.26,65.46 57.35,66.55 v1(57.75,66.55)
  L8_SIG3 w0.114: v1(57.75,66.55) 57.67,66.15 57.67,65.71 57.23,65.27 57.23,64.62 58.31,63.54 58.31,47.04 59.86,45.48 61.81,45.48 63.97,43.32 63.97,41.21 74.98,30.2 v2(74.98,29.26)
  BOTTOM w0.14: U29.9 v2(74.98,29.26)
PA_01/UART0_RXB/FPLL3_DBG_LOCK/: length 65.9
  TOP w0.14: U1.T1 v1(50.15,54.22) ; v1(57.67,65.14) 57.67,65.52 58.25,66.09 P8.190
  L3_SIG1 w0.114: v1(57.67,65.14) 57.3,65.07 55.6,65.07 54.69,64.16 54.69,63.27 54.36,62.94 54.36,60.22 53.21,59.08 53.21,56.72 51.92,55.42 51.59,55.42 50.52,54.36 v1(50.15,54.22)
  L8_SIG3 w0.114: v1(57.67,65.14) 57.67,64.62 58.62,63.67 58.62,47.17 59.99,45.8 61.94,45.8 64.29,43.45 64.29,41.34 75.27,30.35 76.47,30.35 v2(76.93,29.9)
  BOTTOM w0.14: U29.12 v2(76.93,29.9)
PA_02/UART0_RTSB/FLG0/ETH0_PTPA: length 83.3
  TOP w0.14: v1(58.37,65.58) 58.75,65.96 P8.192 ; U1.U3 v1(48.55,55.02)
  L3_SIG1 w0.114: v1(48.55,55.02) 48.18,54.91 47.88,54.62 47.62,54.62 47.35,54.88 47.35,55.15 47.62,55.42 47.87,55.42 48.15,55.7 48.15,59.16 50.05,61.06 50.05,62.73 50.77,63.45 50.77,64.54 53.18,66.95 57,66.95 57.3,66.65 57.3,66.4 57.72,65.98 57.98,65.98 v1(58.37,65.58)
  L8_SIG3 w0.114: v1(58.37,65.58) 58.62,65.33 58.62,64.57 59.26,63.93 59.26,47.55 60.38,46.43 62.2,46.43 64.92,43.71 64.92,41.6 75.44,31.09 77.17,31.09 78.05,30.2 78.05,27.46 76.26,25.66 76.26,23.73 v2(77.58,22.4)
  BOTTOM w0.14: U29.2 v2(77.58,22.4)
PA_03/UART0_CTSB/FLG1/ETH0_PTPA: length 79.1
  TOP w0.14: U1.T3 v1(48.55,54.22) ; v1(59,65.14) 59.25,65.38 P8.194
  L3_SIG1 w0.114: v1(48.55,54.22) 48.95,53.82 49.5,53.82 49.75,54.07 49.75,54.35 50.02,54.62 50.35,54.62 52.78,57.05 52.78,59.61 53.24,60.07 53.24,62.36 54.37,63.49 54.37,64.27 55.45,65.35 57.33,65.35 57.53,65.56 57.82,65.56 58.24,65.14 v1(59,65.14)
  L8_SIG3 w0.114: v2(75.63,24.09) 75.63,25.62 77.67,27.66 77.67,30 76.96,30.71 75.37,30.71 64.6,41.47 64.6,43.58 62.07,46.11 60.19,46.11 58.94,47.36 58.94,63.8 58.06,64.68 58.06,65.3 57.98,65.39 57.98,65.92 58.15,66.09 58.72,66.09 59,65.8 v1(59,65.14)
  BOTTOM w0.14: U29.5 v2(75.63,24.09)
PA_04/UART1_RXB/FPLL0_DBG_LOCK/: length 26
  TOP w0.14: P8.200 60.75,66.12 v1(59.77,65.14) ; U1.R4 v1(47.75,53.42)
  L3_SIG1 w0.114: v1(59.77,65.14) 59.77,64.73 59.3,64.26 57.4,64.26 57.2,64.47 55.91,64.47 55.42,63.98 55.42,62.66 55.77,62.32 55.77,57.59 51.19,53.02 48.15,53.02 v1(47.75,53.42)
PA_05/UART1_TXB/FPLL1_DBG_LOCK: length 23.5
  TOP w0.14: P8.198 60.25,66.38 v1(59.77,65.9) ; U1.R2 v1(49.35,53.42)
  L3_SIG1 w0.114: v1(49.35,53.42) 49.72,53.5 50.03,53.82 50.41,53.82 51.56,54.97 52.65,54.97 55.45,57.76 55.45,62.13 55,62.57 55,64.01 55.77,64.77 57.33,64.77 57.48,64.62 59.11,64.62 59.39,64.9 59.39,65.52 v1(59.77,65.9)
PA_06/UART1_RTSB/SPI5_RDY/FLG2/: length 33.5
  TOP w0.14: P8.202 61.25,65.79 v1(60.59,65.14) ; U1.P6 v1(46.15,52.62)
  L3_SIG1 w0.114: v1(46.15,52.62) 46.55,53.01 47.12,53.01 47.35,53.24 47.35,53.59 47.12,53.82 46.79,53.82 46.56,54.05 46.56,54.33 46.27,54.62 45.95,54.62 45.74,54.82 45.74,55.14 46.02,55.42 46.27,55.42 46.55,55.69 46.55,59.54 48.97,61.96 48.97,64.38 49.49,64.9 50.06,64.9 52.41,67.24 59.63,67.24 60.59,66.28 v1(60.59,65.14)
PA_07/UART1_CTSB/EMSI0_HOST_REG: length 33.5
  TOP w0.14: U1.R5 v1(46.95,53.42) ; P8.204 61.75,65.4 v1(61.48,65.14)
  L3_SIG1 w0.114: v1(46.95,53.42) 46.6,53.51 46.29,53.82 46.01,53.82 45.75,54.07 45.75,54.32 45.47,54.6 45.19,54.6 44.93,54.86 44.93,55.17 45.17,55.4 45.5,55.4 45.75,55.66 45.75,59.25 48.59,62.09 48.59,64.5 49.31,65.23 49.94,65.23 52.24,67.53 59.82,67.53 61.48,65.87 v1(61.48,65.14)
PA_08/TWI0_SCL/PWM0_AH: length 21.7
  TOP w0.14: P8.152 48.75,65.81 v1(50.37,64.19) R137.2 ; U1.P5 v1(46.95,52.62)
  L5_SIG2 w0.114: v1(50.37,64.19) 50.37,61.32 52.22,59.46 52.22,57.48 50.95,56.21 49.99,56.21 49.76,55.98 49.76,55.7 49.48,55.42 49.23,55.42 48.97,55.17 48.97,54.91 48.69,54.64 48.44,54.64 48.16,54.36 48.16,54.08 47.9,53.82 47.57,53.82 47.35,53.59 47.35,53.01 v1(46.95,52.62)
PA_09/TWI0_SDA/PWM0_AL: length 19.5
  TOP w0.14: R136.2 49.35,63.54 v1(49.35,64.19) 48.25,65.2 48.25,66.79 48.25,66.8 P8.150 ; U1.R3 v1(48.55,53.42)
  L3_SIG1 w0.114: v1(49.35,64.19) 49.35,61.84 47.35,59.83 47.35,55.68 47.08,55.42 46.8,55.42 46.55,55.16 46.55,54.85 46.79,54.61 47.12,54.61 47.35,54.38 47.35,54.05 47.58,53.82 48.15,53.82 v1(48.55,53.42)
PA_10/TWI1_SCL/PWM0_BH: length 20.3
  TOP w0.14: U1.P2 v1(49.35,52.62) ; R139.2 v1(52.65,64.19) 52.32,64.19 50.25,66.26 P8.158
  L5_SIG2 w0.114: v1(52.65,64.19) 53.21,63.63 53.21,56.67 50.38,53.84 50.03,53.84 49.73,53.54 49.73,53.26 49.35,52.88 v1(49.35,52.62)
PA_11/TWI1_SDA/PWM0_BL: length 20.6
  TOP w0.14: U1.P3 v1(48.55,52.62) ; P8.156 49.75,66.18 51.51,64.41 v1(51.51,64.19) R138.2
  L5_SIG2 w0.114: v1(48.55,52.62) 48.97,53.04 48.97,53.57 49.24,53.84 49.52,53.84 49.76,54.08 49.76,54.38 49.99,54.61 50.47,54.61 52.86,57 52.86,60.24 52.1,61.01 52.1,63.6 v1(51.51,64.19)
PA_12/TWI2_SCL/PWM0_CH: length 21.3
  TOP w0.14: U1.R1 v1(50.15,53.42) ; P8.164 51.75,66.26 53.12,64.88 v1(53.67,64.88) 54.66,63.89 54.66,63.69 R141.2
  L5_SIG2 w0.114: v1(50.15,53.42) 51.38,53.42 52.02,54.05 52.02,54.75 54.33,57.06 54.33,64.22 v1(53.67,64.88)
PA_13/TWI2_SDA/PWM0_CL: length 24.8
  TOP w0.14: R140.2 53.8,64.03 v1(53.66,64.17) 53.25,64.17 51.25,66.18 P8.162 ; U1.P4 v1(47.75,52.62)
  L5_SIG2 w0.114: v1(53.66,64.17) 53.24,64.59 51.36,64.59 50.98,64.21 50.98,61.32 52.55,59.75 52.55,57.25 50.72,55.42 49.99,55.42 49.73,55.17 49.73,54.86 49.48,54.61 49.2,54.61 48.95,54.36 48.95,54.08 48.69,53.82 48.41,53.82 48.15,53.56 48.15,53.01 v1(47.75,52.62)
PA_14/TWI3_SCL/TM0_TMR9/HADC0_E: length 27.9
  TOP w0.14: R133.2 v1(66.37,65.11) ; U1.P1 v1(50.15,52.62)
  L5_SIG2 w0.114: v1(50.15,52.62) 51.55,52.62 52.73,53.8 52.73,54.48 59.18,60.93 59.18,62.46 61.01,64.29 63.83,64.29 65.03,65.49 65.98,65.49 v1(66.37,65.11)
  BOTTOM w0.14: P8.227 67.5,66.23 v1(66.37,65.11)
PA_15/TWI3_SDA/TM0_TMR10/SPI5_S: length 28.2
  TOP w0.14: U1.N2 v1(49.35,51.82) ; R132.2 v1(65.23,65.11)
  L5_SIG2 w0.114: v1(65.23,65.11) 64.01,63.89 61.06,63.89 59.5,62.33 59.5,60.74 53.16,54.4 53.16,53.75 51.64,52.22 50.01,52.22 49.61,51.82 v1(49.35,51.82)
  BOTTOM w0.14: v1(65.23,65.11) 65.83,65.71 66.37,65.71 67,66.34 P8.225
PB_00/TWI4_SCL/TM0_TMR14/SPI0_S: length 33.9
  TOP w0.14: R135.2 v1(68.66,65.11) ; U1.N5 v1(46.95,51.82)
  L5_SIG2 w0.114: v1(46.95,51.82) 47.36,52.22 49.53,52.22 49.73,52.43 49.73,52.73 50.01,53.01 51.46,53.01 52.37,53.92 52.37,54.57 58.8,61 58.8,62.53 60.93,64.66 63.7,64.66 64.96,65.91 67.85,65.91 v1(68.66,65.11)
  BOTTOM w0.14: v1(68.66,65.11) 69,65.44 P8.233
PB_01/TWI4_SDA/TM0_TMR15/SPI0_S: length 32.1
  TOP w0.14: U1.N4 v1(47.75,51.82) ; R134.2 v1(67.51,65.11)
  L5_SIG2 w0.114: v1(67.51,65.11) 65.32,62.92 60.53,62.92 59.82,62.2 59.82,60.53 54.25,54.96 54.25,53.79 51.87,51.41 48.16,51.41 v1(47.75,51.82)
  BOTTOM w0.14: P8.231 68.5,66.09 v1(67.51,65.11)
PB_02/TWI5_SCL/SPI5_SEL2B: length 138.2
  TOP w0.14: U1.M2 v1(49.35,51.02) ; v2(60.72,61.4) R115.2 61.85,61.71 U17.1 ; U4.23 42.63,3.75 42.37,3.48 42.37,3.1 v2(42.62,2.59)
  L3_SIG1 w0.114: v2(8.87,30.06) 10.62,28.31 28.02,28.31 36.5,19.82 43.19,19.82 v2(43.24,19.88)
  L5_SIG2 w0.114: v2(43.24,19.88) 43.29,19.82 44.42,19.82 46.56,17.69 46.56,16.73 47.78,15.51 50.43,15.51 55.4,20.49 55.4,43.01 54.02,44.39 51.04,44.39 50.39,45.03 48.39,45.03 48.16,45.26 48.16,45.59 47.96,45.8 47.62,45.8 47.35,46.08 47.35,46.38 47.12,46.61 46.84,46.61 46.56,46.89 46.56,47.14 46.28,47.42 46,47.42 45.75,47.68 45.75,47.96 45.49,48.21 45.24,48.21 44.96,48.49 44.96,49.58 46.02,50.65 48.98,50.65 v1(49.35,51.02) 51.92,51.02 54.56,53.66 54.56,54.83 60.18,60.44 60.18,60.86 v2(60.72,61.4)
  L10_SIG4 w0.114: v2(43.24,19.88) 43.89,19.23 43.89,17.96 43.13,17.2 43.13,3.1 v2(42.62,2.59)
  BOTTOM w0.14: U16.2 9.11,29.82 v2(8.87,30.06)
PB_03/TWI5_SDA/SPI5_SEL3B: length 138.3
  TOP w0.14: v2(60.72,60.11) R117.2 61.85,59.81 U17.3 ; U4.22 42.5,4.25 41.99,3.73 41.99,3.1 v2(41.86,2.59) ; U1.L6 v1(46.15,49.42)
  L3_SIG1 w0.114: v2(8.33,30.53) 8.33,29.85 10.19,27.99 27.89,27.99 36.56,19.32 43.03,19.32 v2(43.26,19.1)
  L5_SIG2 w0.114: v2(43.26,19.1) 43.48,19.32 44.47,19.32 46.18,17.61 46.18,16.66 47.64,15.2 50.56,15.2 55.72,20.36 55.72,43.14 54.04,44.82 51.14,44.82 50.14,45.82 48.39,45.82 48.16,46.05 48.16,46.41 47.94,46.63 47.57,46.63 47.35,46.86 47.35,47.17 47.09,47.42 46.79,47.42 46.56,47.65 46.56,47.98 46.33,48.21 46,48.21 45.75,48.46 45.75,49.01 v1(46.15,49.42) 46.28,49.81 46.84,50.37 49.84,50.37 50.04,50.16 51.52,50.16 54.91,53.56 54.91,54.73 60.3,60.11 v2(60.72,60.11)
  L10_SIG4 w0.114: v2(43.26,19.1) 42.62,18.47 42.62,3.35 v2(41.86,2.59)
  BOTTOM w0.14: U16.1 8.61,29.62 8.33,29.9 v2(8.33,30.53)
PB_04/MLB0_DAT/TM0_TMR11: length 26.9
  TOP w0.14: U1.M5 v1(46.95,51.02) ; P8.172 53.75,66.45 54.66,65.53 55.25,65.53 56.72,64.06 v1(56.72,63.74)
  L3_SIG1 w0.114: v1(56.72,63.74) 56.72,64.07 56.6,64.19 56.08,64.19 55.78,63.89 55.78,62.84 56.08,62.53 56.08,57.46 50.84,52.22 47.57,52.22 47.35,52 47.35,51.42 v1(46.95,51.02)
PB_05/MLB0_SIG/TM0_TMR12: length 23.6
  TOP w0.14: P8.170 53.25,66.44 54.56,65.13 55.09,65.13 56.16,64.06 v1(56.16,63.75) ; U1.N3 v1(48.55,51.82)
  L3_SIG1 w0.114: v1(56.16,63.75) 56.16,62.97 56.4,62.73 56.4,57.32 50.5,51.42 49.22,51.42 49.09,51.54 49.09,51.54 48.91,51.73 v1(48.55,51.82)
PB_06/MLB0_CLK/TM0_TMR13/TM0_CL: length 26.8
  TOP w0.14: v1(56.72,63.04) 56.16,63.04 55.68,63.53 55.68,63.88 54.79,64.77 54.38,64.77 52.75,66.41 P8.168 ; U1.M4 v1(47.75,51.02)
  L3_SIG1 w0.114: v1(47.75,51.02) 48.14,51.41 48.69,51.41 48.95,51.16 48.95,50.9 49.2,50.65 49.66,50.65 49.99,50.98 51.48,50.98 56.72,56.22 v1(56.72,63.04)
